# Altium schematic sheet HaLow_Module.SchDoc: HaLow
size A3; Author: J. Garnier; DrawnBy: J. Garnier; SheetNumber: 3; SheetTotal: 8
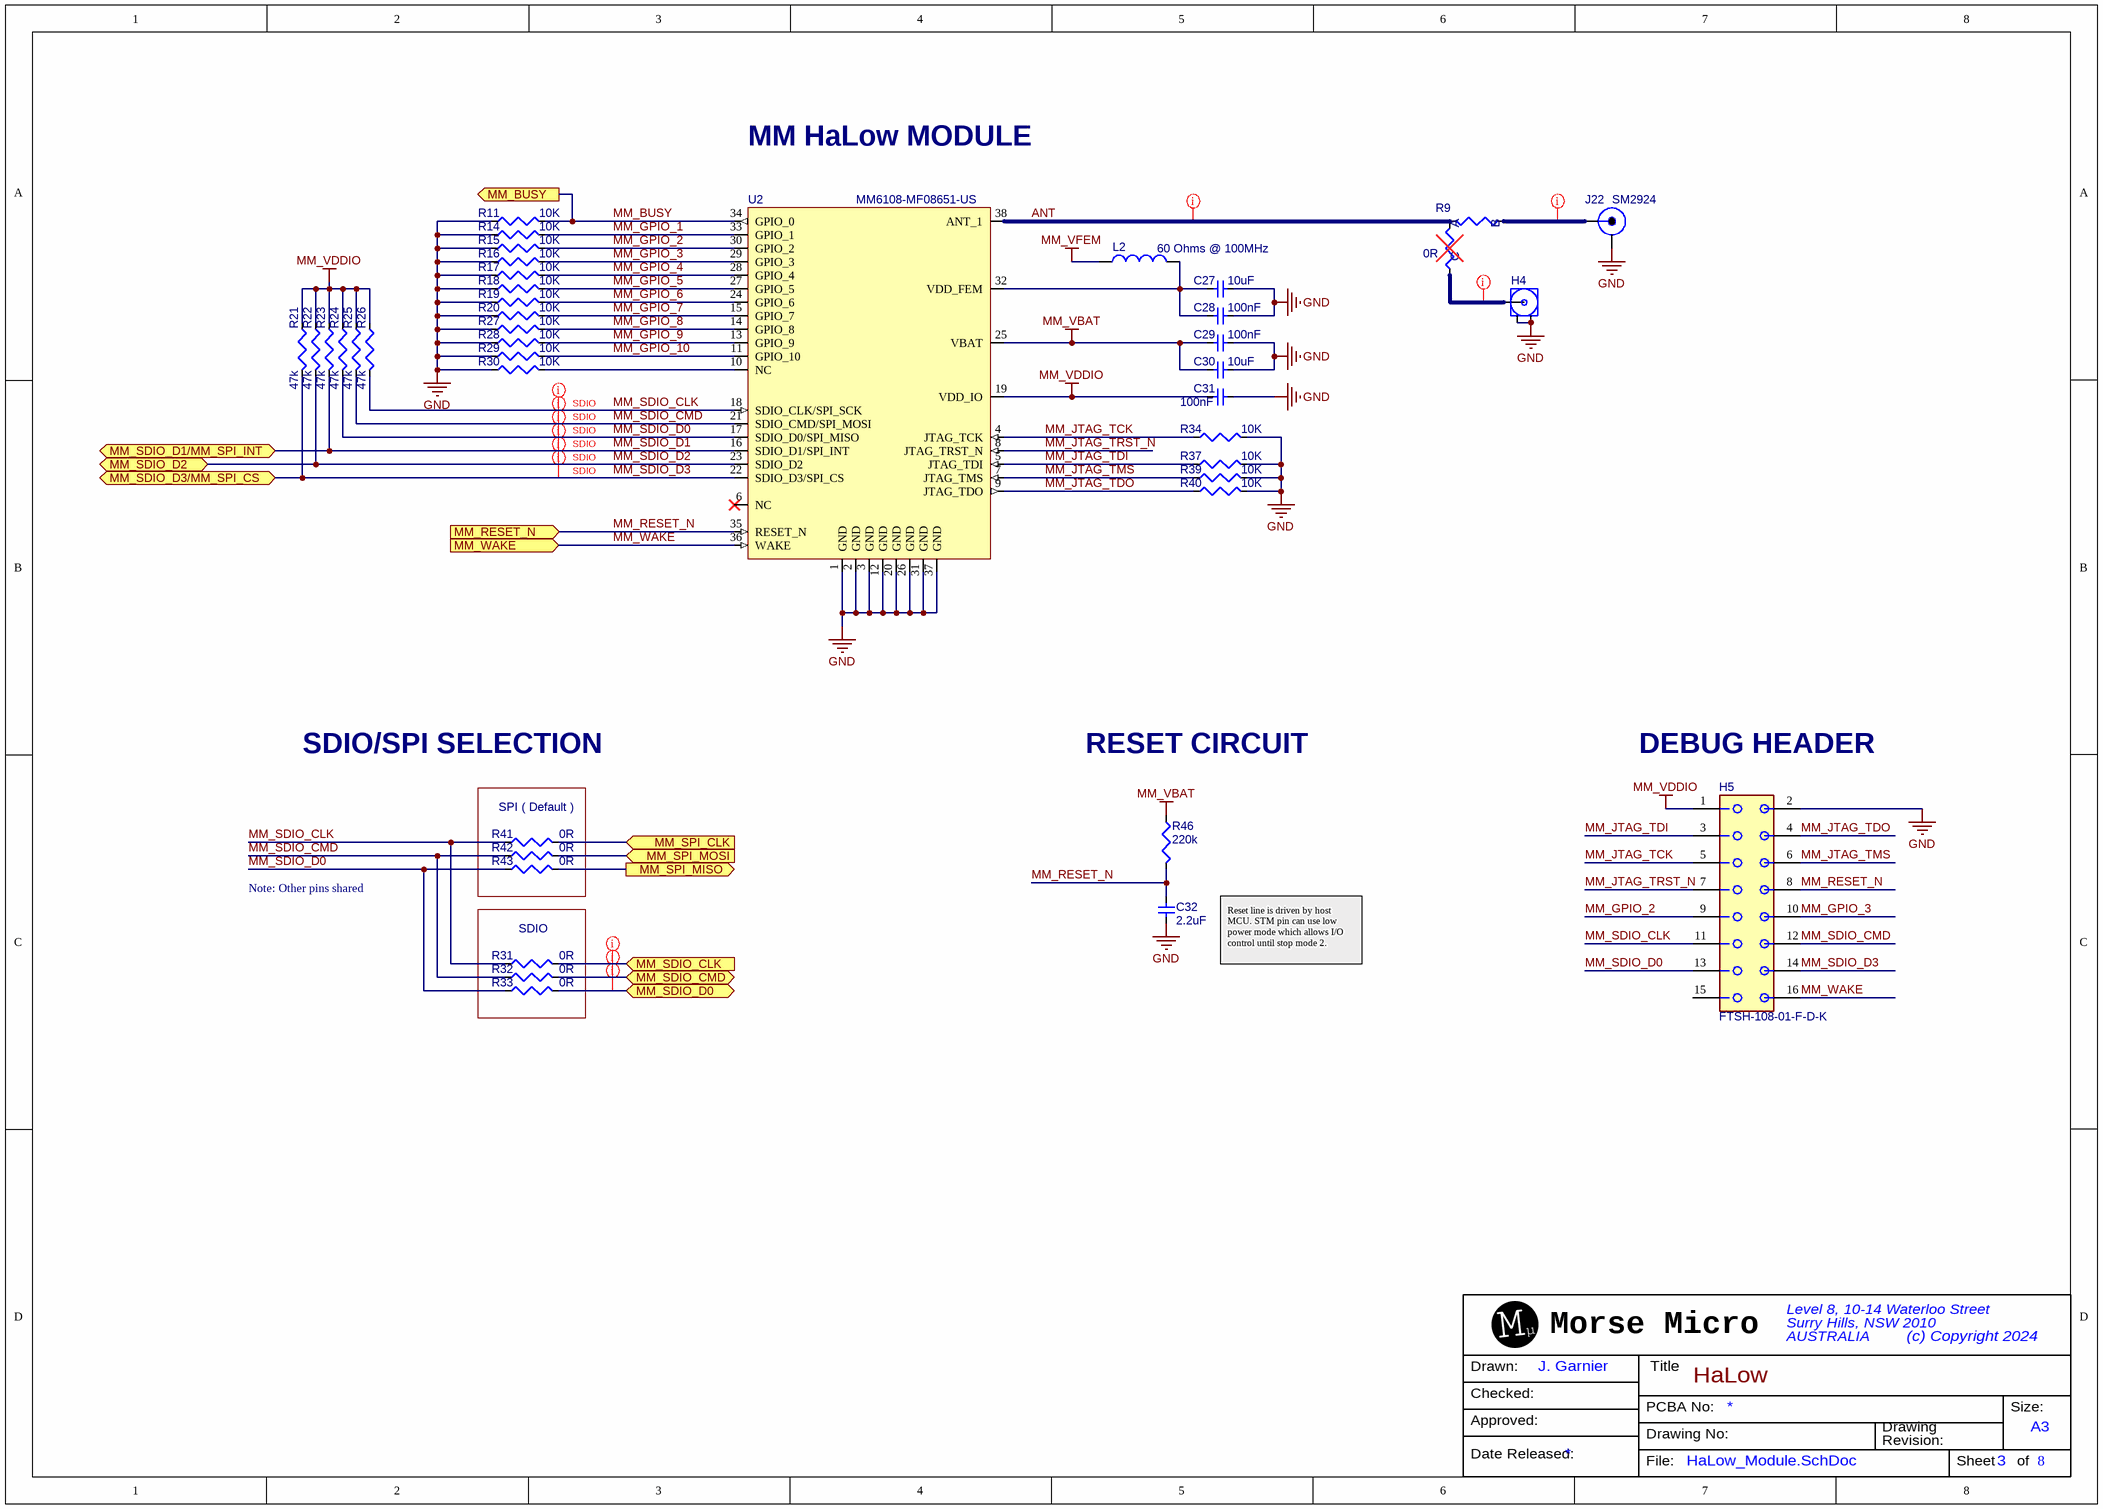
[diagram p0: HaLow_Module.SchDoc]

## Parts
C27  value 10uF  [0402_cap]  (hidden comment: CL05A106MP8NUB8)
C28  value 100nF  [0402_cap]  (hidden comment: C1005X7R1H104K050BE)
C29  value 100nF  [0402_cap]  (hidden comment: C1005X7R1H104K050BE)
C30  value 10uF  [0402_cap]  (hidden comment: CL05A106MP8NUB8)
C31  value 100nF  [0402_cap]  (hidden comment: C1005X7R1H104K050BE)
C32  value 2.2uF  [CAPC1005X06N]  (hidden comment: GRM155R61E225ME15D)
H4  U.FL-R-SMT  [U_FL-R-SMT]  (value not drawn)
H5  FTSH-108-01-F-D-K  [FTSH_108_D_K]
J22  SM2924  [SM2924-Footprint-1]
L2  value 60 Ohms @ 100MHz  [0402_ind]  (hidden comment: BLM15PX600SN1D)
R9  value 0R  [0603_RES_AB_RA]  (hidden comment: RES_AB)
R11  value 10K  [RESC1005X04N]  (hidden comment: ERJ-2RKF1002X)
R14  value 10K  [RESC1005X04N]  (hidden comment: ERJ-2RKF1002X)
R15  value 10K  [RESC1005X04N]  (hidden comment: ERJ-2RKF1002X)
R16  value 10K  [RESC1005X04N]  (hidden comment: ERJ-2RKF1002X)
R17  value 10K  [RESC1005X04N]  (hidden comment: ERJ-2RKF1002X)
R18  value 10K  [RESC1005X04N]  (hidden comment: ERJ-2RKF1002X)
R19  value 10K  [RESC1005X04N]  (hidden comment: ERJ-2RKF1002X)
R20  value 10K  [RESC1005X04N]  (hidden comment: ERJ-2RKF1002X)
R21  value 47k  [RESC1005X04N]  (hidden comment: MCR01MZPF4702)
R22  value 47k  [RESC1005X04N]  (hidden comment: MCR01MZPF4702)
R23  value 47k  [RESC1005X04N]  (hidden comment: MCR01MZPF4702)
R24  value 47k  [RESC1005X04N]  (hidden comment: MCR01MZPF4702)
R25  value 47k  [RESC1005X04N]  (hidden comment: MCR01MZPF4702)
R26  value 47k  [RESC1005X04N]  (hidden comment: MCR01MZPF4702)
R27  value 10K  [RESC1005X04N]  (hidden comment: ERJ-2RKF1002X)
R28  value 10K  [RESC1005X04N]  (hidden comment: ERJ-2RKF1002X)
R29  value 10K  [RESC1005X04N]  (hidden comment: ERJ-2RKF1002X)
R30  value 10K  [RESC1005X04N]  (hidden comment: ERJ-2RKF1002X)
R31  value 0R  [RESC1608X06N]  (hidden comment: RC0603JR-070RL)
R32  value 0R  [RESC1608X06N]  (hidden comment: RC0603JR-070RL)
R33  value 0R  [RESC1608X06N]  (hidden comment: RC0603JR-070RL)
R34  value 10K  [RESC1005X04N]  (hidden comment: ERJ-2RKF1002X)
R37  value 10K  [RESC1005X04N]  (hidden comment: ERJ-2RKF1002X)
R39  value 10K  [RESC1005X04N]  (hidden comment: ERJ-2RKF1002X)
R40  value 10K  [RESC1005X04N]  (hidden comment: ERJ-2RKF1002X)
R41  value 0R  [RESC1608X06N]  (hidden comment: RC0603JR-070RL)
R42  value 0R  [RESC1608X06N]  (hidden comment: RC0603JR-070RL)
R43  value 0R  [RESC1608X06N]  (hidden comment: RC0603JR-070RL)
R46  value 220k  [RESC1005X04N]  (hidden comment: RC0402FR-07220KL)
U2  MM6108-MF08651-US  [MF04]

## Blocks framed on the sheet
SPI ( Default ): R41-R43
SDIO: R31-R33

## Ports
MM_BUSY (out, see Main[2A], STM_MCU[5C]), MM_RESET_N (in, see Main[2A], STM_MCU[8C]), MM_SDIO_CLK (in, see Main[2A], STM_MCU[8C]), MM_SDIO_CMD (bidir, see Main[2A], STM_MCU[8C]), MM_SDIO_D0 (bidir, see Main[2A], STM_MCU[5C]), MM_SDIO_D1/MM_SPI_INT (bidir, see Main[2A], STM_MCU[4C]), MM_SDIO_D2 (bidir, see Main[2B], STM_MCU[5C]), MM_SDIO_D3/MM_SPI_CS (bidir, see Main[2B], STM_MCU[4C]), MM_SPI_CLK (in, see Main[2B], STM_MCU[8B]), MM_SPI_MISO (out, see Main[2B], STM_MCU[8B]), MM_SPI_MOSI (in, see Main[2B], STM_MCU[8B]), MM_WAKE (in, see Main[2A], STM_MCU[8B])

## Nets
GND: C27.2 C28.2 C29.2 C30.2 C31.2 C32.2 H4.2 H4.3 H5.2 J22.2 R11.1 R14.1 R15.1 R16.1 R17.1 R18.1 R19.1 R20.1 R27.1 R28.1 R29.1 R30.1 R34.2 R37.2 R39.2 R40.2 U2.1(GND) U2.2(GND) U2.3(GND) U2.12(GND) U2.20(GND) U2.26(GND) U2.31(GND) U2.37(GND)
MM_VBAT: C29.1 C30.1 R46.1 U2.25(VBAT)
MM_VDDIO: C31.1 H5.1 R21.1 R22.1 R23.1 R24.1 R25.1 R26.1 U2.19(VDD_IO)
MM_VFEM: L2.2
ANT: R9.A U2.38(ANT_1)
MM_BUSY: R11.2 U2.34(GPIO_0) ; port MM_BUSY
MM_GPIO_1: R14.2 U2.33(GPIO_1)
MM_GPIO_2: H5.9 R15.2 U2.30(GPIO_2)
MM_GPIO_3: H5.10 R16.2 U2.29(GPIO_3)
MM_GPIO_4: R17.2 U2.28(GPIO_4)
MM_GPIO_5: R18.2 U2.27(GPIO_5)
MM_GPIO_6: R19.2 U2.24(GPIO_6)
MM_GPIO_7: R20.2 U2.15(GPIO_7)
MM_GPIO_8: R27.2 U2.14(GPIO_8)
MM_GPIO_9: R28.2 U2.13(GPIO_9)
MM_GPIO_10: R29.2 U2.11(GPIO_10)
MM_JTAG_TCK: H5.5 R34.1 U2.4(JTAG_TCK)
MM_JTAG_TDI: H5.3 R37.1 U2.5(JTAG_TDI)
MM_JTAG_TDO: H5.4 R40.1 U2.9(JTAG_TDO)
MM_JTAG_TMS: H5.6 R39.1 U2.7(JTAG_TMS)
MM_JTAG_TRST_N: H5.7 U2.8(JTAG_TRST_N)
MM_RESET_N: C32.1 H5.8 R46.2 U2.35(RESET_N) ; port MM_RESET_N
MM_SDIO_CLK: H5.11 R26.2 R31.2 R41.1 U2.18(SDIO_CLK/SPI_SCK)
MM_SDIO_CLK: R31.1 ; port MM_SDIO_CLK  [a separate net that carries the same name]
MM_SDIO_CMD: H5.12 R25.2 R32.2 R42.1 U2.21(SDIO_CMD/SPI_MOSI)
MM_SDIO_CMD: R32.1 ; port MM_SDIO_CMD  [a separate net that carries the same name]
MM_SDIO_D0: H5.13 R24.2 R33.2 R43.1 U2.17(SDIO_D0/SPI_MISO)
MM_SDIO_D0: R33.1 ; port MM_SDIO_D0  [a separate net that carries the same name]
MM_SDIO_D1: R23.2 U2.16(SDIO_D1/SPI_INT) ; port MM_SDIO_D1/MM_SPI_INT
MM_SDIO_D2: R22.2 U2.23(SDIO_D2) ; port MM_SDIO_D2
MM_SDIO_D3: H5.14 R21.2 U2.22(SDIO_D3/SPI_CS) ; port MM_SDIO_D3/MM_SPI_CS
MM_SPI_CLK: R41.2 ; port MM_SPI_CLK
MM_SPI_MISO: R43.2 ; port MM_SPI_MISO
MM_SPI_MOSI: R42.2 ; port MM_SPI_MOSI
MM_WAKE: H5.16 U2.36(WAKE) ; port MM_WAKE
NetC27_1: C27.1 C28.1 L2.1 U2.32(VDD_FEM)
NetH4_1: H4.1 R9.C
NetJ22_1: J22.1 R9.B
NetR30_2: R30.2 U2.10(NC)

Not connected (* = marked no-connect by the designer): H5 15; U2 6(NC)*

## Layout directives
net class SDIO: MM_SDIO_CLK, MM_SDIO_CMD, MM_SDIO_D0, MM_SDIO_D1, MM_SDIO_D2, MM_SDIO_D3
net class 50 OHMs: ANT, NetH4_1, NetJ22_1
net class SDIO_2: MM_SDIO_CLK, MM_SDIO_CMD, MM_SDIO_D0

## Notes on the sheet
- MM HaLow MODULE
- SDIO/SPI SELECTION
- RESET CIRCUIT
- (near H5) DEBUG HEADER
- Note: Other pins shared
- Reset line is driven by host MCU. STM pin can use low power mode which allows I/O control until stop mode 2.

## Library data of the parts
C27 C30 = CAP0046-13: CAP CER 10UF 10V 20% X5R 0402; Generic Allowed: Yes; Subtype: Ceramic
C28 C29 C31 = CAP0068-11: CAP CER 100NF 50V ±10% X7R 0402; Subtype: Ceramic; Generic Allowed: Yes
C32 = CAP0055-10: CAP CER 2.2UF 25V ±20% X5R 0402; Subtype: Ceramic; Generic Allowed: Yes
H4 = JCK0091-1: U.FL RF Connector; Generic Allowed: Yes
H5 = JCK0086-2: CONN,Vertical FTSH Series,0.05"16 Pins, Through Hole; Generic Allowed: No
J22 = JCK0138-4: Wanshih RF SMD SMA connector with 2 GND pillars - Smaller Connector Barrel
L2 = IND0062-6: BEAD 60OHMS 2500MA 32 MOHM; DC Resistance: 32mOhm; Generic Allowed: Yes; Current: 2.5A
R9 = RES0280: Ohms Jumper Chip Resistor 0603 ( 1608 Metric) - RES_AC; Manufacturer 1: Rohm; Manufacturer Part Number 1: MCR03EZPJ000; Generic Allowed: Yes; Power: 1/10W; Tolerance: 5%
R11 R14-R20 R27-R30 R34 R37 R39 R40 = RES0002-8: RES SMD 10K OHM ±1% 1/10W 0402; Generic Allowed: Yes
R21-R26 = RES0086-8: RES SMD 47K OHM ±1% 1/16W 0402; Generic Allowed: Yes
R31-R33 R41-R43 = RES0119-6: RES SMD 0R OHM ±5% 1/10W 0603; Generic Allowed: Yes
R46 = RES0064-8: RES SMD 220K OHM ±1% 1/16W 0402; Generic Allowed: Yes
U2 = MOD0010-3: MM61xx-MF08; Item_Number: MOD0061; Value: MM61xx-MF08251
